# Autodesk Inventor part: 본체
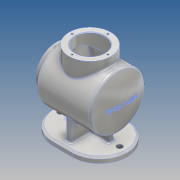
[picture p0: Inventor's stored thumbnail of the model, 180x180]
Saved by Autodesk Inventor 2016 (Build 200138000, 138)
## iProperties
Created: 2016-04
Part Number: 본체
Material: 알루미늄 6061
Document SubType Name: Modeling
Designer: Administrator
Density: 2.7 g/cm^3
Appearance: 알루미늄 - 평지
Mass: 1016.92 g
Surface Area: 1209.17 cm^2
Volume: 376.636 cm^3
Author: Administrator
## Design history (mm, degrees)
sketch "스케치1"
  geometry: L1 (-17.5, -50)-(17.5, -50); L2 (67.5, 0)-(67.5, 0); L3 (17.5, 50)-(-17.5, 50); L4 (-67.5, 0)-(-67.5, 0); L5 (-67.5, -50)-(67.5, 50); L6 (67.5, -50)-(-67.5, 50); A1 r 50 centre (-17.5, 0) between (-17.5, 50) and (-67.5, 0); A2 r 50 centre (-17.5, 0) between (-67.5, 0) and (-17.5, -50); A3 r 50 centre (17.5, 0) between (17.5, -50) and (67.5, 0); A4 r 50 centre (17.5, 0) between (67.5, 0) and (17.5, 50); 1 further point
  constraints: 12 end point, 8 point on circle, 8 point on line, 8 tangent, 4 centre point, 3 equal radius, 2 midpoint, 2 parallel, 1 horizontal, 1 perpendicular
  dimensions: "d0" = 135 distance of L6.end L5.end; "d1" = 100 distance of L5.end L6.start; "d2" = 50 radius of A1
extrude "돌출1" new body sketch "스케치1" distance "d3" = 10; taper "d4" = 0 deg
sketch "스케치2"
  geometry: 3 further points
  constraints: 2 horizontal alignment
  dimensions: "d8" = 54 distance of point (0, 0) point (54, 0); "d9" = 54 distance of point (0, 0) point (-54, 0)
hole "구멍1" sketch "스케치2" at (54, 0), (-54, 0) diameter "d10" = 10; stored, may be unused: countersink angle "d14" = 90 deg, drill point angle "d16" = 118 deg; dims "d11" = 6, "d12" = 4, "d13" = 2, "d15" = 8
sketch "스케치4"
  geometry: L1 (61, 79)-(-61, 79); L2 (49, 129)-(-50.087, 129); L3 (49, 129)-(49, 117); L4 (49, 117)-(61, 117); L5 (61, 117)-(61, 79); L6 (-17.5, 0)-(17.5, 0) reference; A1 r 120 centre (59, 79) between (-50.087, 129) and (-61, 79); 3 further points
  constraints: 10 end point, 3 horizontal, 2 midpoint, 2 perpendicular, 2 point on circle, 1 centre point, 1 point on line, 1 vertical alignment
  dimensions: "d19" = 79 distance from line of point (0, 0) L1; "d33" = 110 distance from line of L1.end L3; "d34" = 120 radius of A1; "d35" = 100 diameter of L2 L1; "d37" = 12 distance of L3.end L4.end; "d38" = 76 diameter of L4 L1
revolve "회전1" sketch "스케치4" stored, may be unused: angle "d39" = 90 deg
node "작업 평면1"
sketch "스케치6"
  geometry: C1 r 38 at (0, 0); 1 further point
  constraints: 1 centre point, 1 coincident
  dimensions: "d41" = 76 diameter of C1
extrude "돌출2" join sketch "스케치6" distance "d42" = 65; taper "d43" = 0 deg
sketch "스케치7"
  geometry: L1 (61, 41)-(61, 117) reference; L2 (61, 79)-(-90.061, 79); L3 (61, 106)-(46, 106); L4 (46, 106)-(46, 126); L5 (46, 126)-(-48.145, 126); L6 (38, 144)-(-38, 144) reference; L7 (-50.087, 129)-(49, 129) reference; L8 (49, 117)-(61, 117) reference; L9 (49, 29)-(49, 129) reference; L10 (38, 129)-(38, 144) reference; L11 (-38, 129)-(-38, 144) reference; A1 r 120 centre (59, 79) between (-50.087, 129) and (-50.087, 29) reference; A2 r 117 centre (59, 79) between (-48.145, 126) and (-58, 79); 3 further points
  constraints: 8 end point, 3 point on line, 2 horizontal, 2 midpoint, 2 perpendicular, 2 point on circle, 1 centre point, 1 coincident
  dimensions: "d46" = 54 diameter of L3 L2; "d47" = 3 distance between parallel lines of L9 L4; "d48" = 3 distance between parallel lines of L7 L5; "d113" = 117 radius of A2
revolve "회전2" sketch "스케치7" stored, may be unused: angle "d50" = 90 deg
sketch "스케치8"
  geometry: 1 further point
sketch "스케치9"
  geometry: C1 r 38 at (0, 0) reference; C2 r 27 at (0, 0)
  constraints: 1 centre point, 1 coincident
  dimensions: "d51" = 54 diameter of C2
extrude "돌출3" cut sketch "스케치9" distance "d52" = 65; taper "d53" = 0 deg
sketch "스케치11"
  geometry: L1 (-50.087, 29)-(49, 29) reference; L2 (34.71, 40)-(40, 10); L3 (67.5, 10)-(17.5, 10) reference; L4 (-34.71, 40)-(-40, 10); L5 (-17.5, 10)-(-67.5, 10) reference; L6 (40, 10)-(-40, 10); L7 (34.71, 40)-(-34.71, 40); 1 further point
  constraints: 8 end point, 2 point on line, 1 collinear, 1 horizontal
  dimensions: "d54" = 100 deg angle of L5 L4; "d55" = 100 deg angle of L3 L2; "d56" = 40 horizontal distance of point (0, 0) L2.end; "d57" = 40 horizontal distance of point (0, 0) L4.end; "d58" = 40 distance from line of point (0, 0) L7
extrude "돌출4" join sketch "스케치11" stored distance "d59" = 10; taper "d60" = 0 deg
sketch "스케치12"
  geometry: C1 r 47 at (0, 79) reference; C2 r 47 at (0, 79); 1 further point
  constraints: 1 centre point, 1 coincident, 1 concentric
extrude "돌출5" cut sketch "스케치12" stored distance "d61" = 80; taper "d62" = 0 deg
sketch "스케치13"
  geometry: L1 (40, 5)-(40, 55); L2 (40, 55)-(-40, 55); L3 (-40, 55)-(-40, 5); L4 (50, 0)-(-50, 0) reference; L5 (50, 0)-(50, 10) reference; L6 (-50, 10)-(50, 10) reference; L7 (-50, 0)-(-50, 10) reference; L8 (40, 5)-(-40, 5); 1 further point
  constraints: 8 end point, 2 perpendicular, 1 parallel, 1 vertical
  dimensions: "d63" = 40 distance from line of point (0, 0) L1; "d64" = 40 distance from line of L3 point (0, 0); "d65" = 55 distance from line of point (0, 0) L2; "d66" = 5 distance from line of L4 L3.end
extrude "돌출6" join sketch "스케치13" stored distance "d67" = 10; taper "d68" = 0 deg
sketch "스케치14"
  geometry: C1 r 47 at (0, 79) reference; C2 r 47 at (0, 79); 1 further point
  constraints: 1 centre point, 1 coincident, 1 concentric
extrude "돌출7" cut sketch "스케치14" stored distance "d69" = 80; taper "d70" = 0 deg
sketch "스케치15"
  geometry: C1 r 27 at (0, 0) reference; 2 further points
  constraints: 1 horizontal alignment
  dimensions: "d71" = 32.5 distance of C1.centre point (32.5, 0)
hole "구멍2" sketch "스케치15" at (32.5, 0) diameter "d72" = 3.242; stored, may be unused: countersink angle "d76" = 90 deg, drill point angle "d78" = 118 deg; dims "d73" = 8, "d74" = 4, "d75" = 2, "d77" = 10
sketch "스케치16"
  geometry: C1 r 27 at (0, 0) reference; 1 further point
  constraints: 1 horizontal alignment
  dimensions: "d82" = 32.5 distance of C1.centre point (32.5, 0)
hole "구멍3" sketch "스케치16" at (32.5, 0) diameter "d83" = 3.242; stored, may be unused: countersink angle "d87" = 90 deg, drill point angle "d89" = 118 deg; dims "d84" = 8, "d85" = 4, "d86" = 2, "d88" = 10
chamfer "모따기1" distance "d93" = 1; stored, may be unused: second distance "d94" = 2, angle "d95" = 45 deg
fillet "모깎기1" dims "d96" = 2
chamfer "모따기2" distance "d97" = 3; stored, may be unused: second distance "d98" = 2, angle "d99" = 45 deg
fillet "모깎기2" dims "d100" = 5
fillet "모깎기3" dims "d101" = 3
node "작업 평면5"
sketch "스케치21"
  geometry: L1 (79, -50)-(79, 50) reference; 3 further points
  constraints: 1 horizontal alignment, 1 midpoint, 1 other
  dimensions: "d106" = 79 distance from line of L1 point (0, 0)
feature "엠보싱1" sketch "스케치21" dims "d0" = 135, "d1" = 100, "d2" = 50, "d107" = 0.5, "d108" = 0
node "솔리드1"
pattern_circular "원형 패턴1" dims angle "d80" = 360 deg
pattern_circular "원형 패턴2" dims angle "d91" = 360 deg
node "투영된 루프2"
node "투영된 루프3"
other parameters: "d40" = 79, "d105" = 109
